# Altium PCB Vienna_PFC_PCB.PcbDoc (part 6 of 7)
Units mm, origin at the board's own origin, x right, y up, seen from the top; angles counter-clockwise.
Board outline 447.04 x 302.51 mm, 6 copper layers (Top Layer, Signal Layer 1, Signal Layer 2, Signal Layer 3, Signal Layer 4, Bottom Layer), stack 1.231 mm thick; 630 components, 255 nets, 1656 pads, 941 vias.
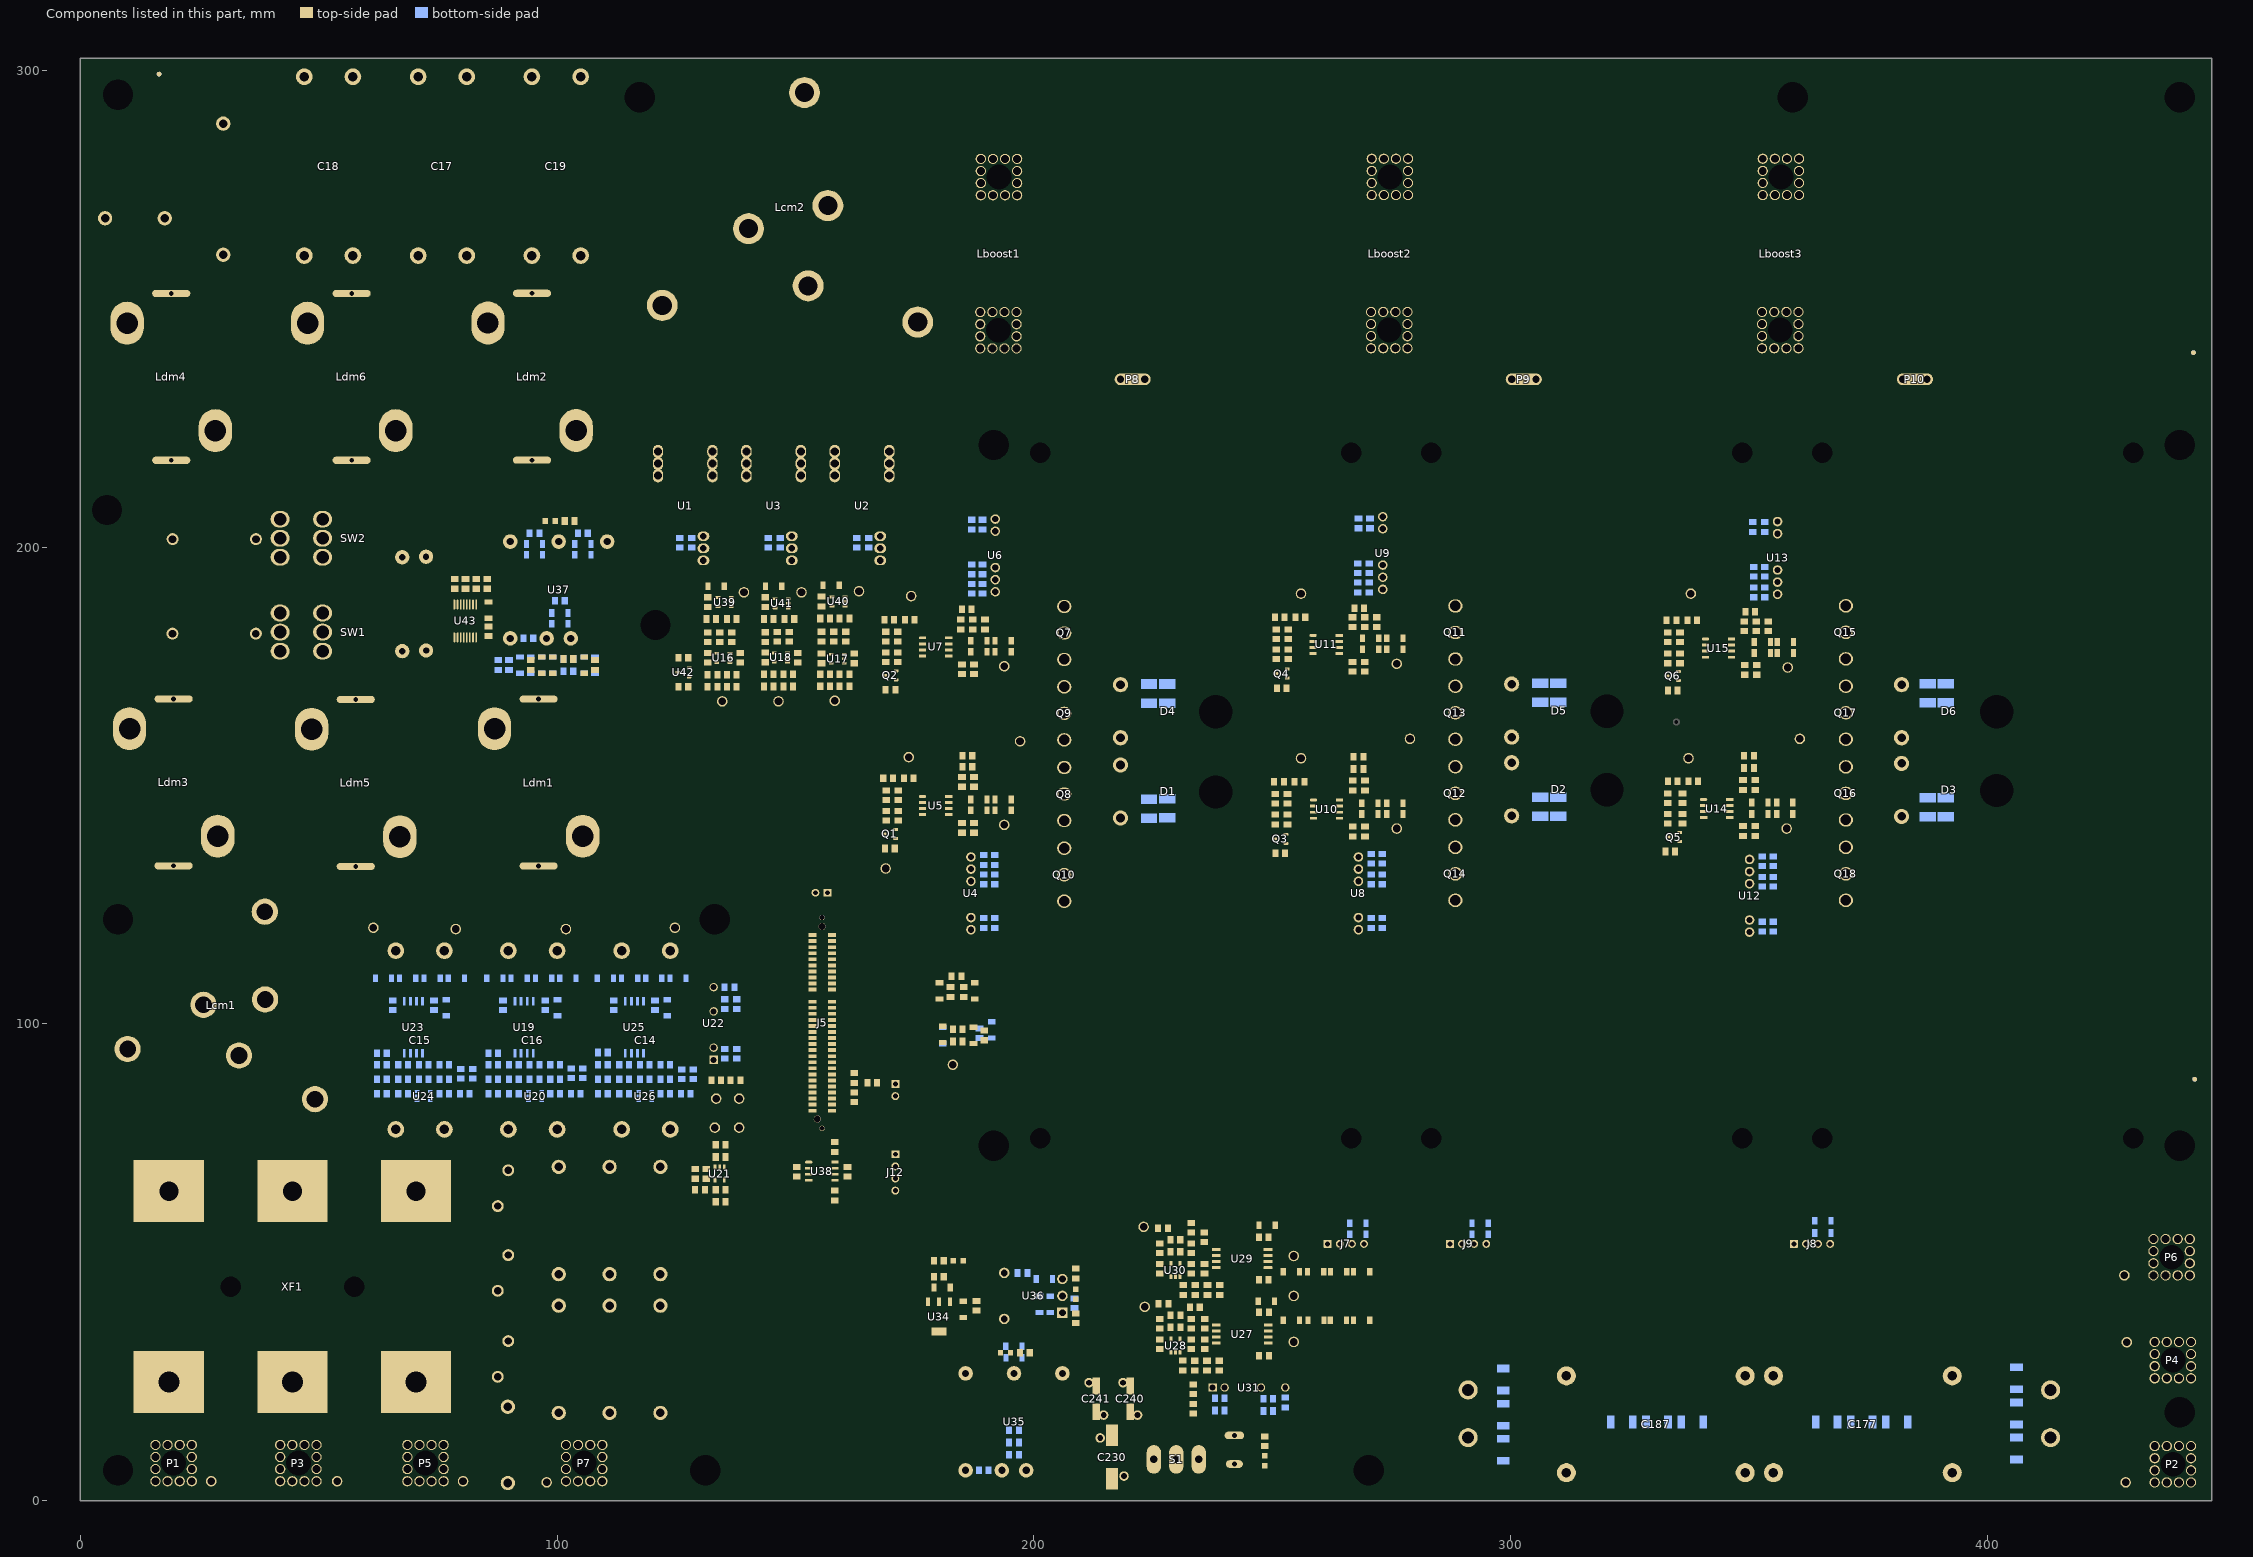
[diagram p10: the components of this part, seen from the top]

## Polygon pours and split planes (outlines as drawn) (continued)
NetLdm2_1 on Signal Layer 4 "NONET_L-01_P-001" (solid, remove dead copper, pour order 1302): 27 vertices, not listed, extent 46.99,175.26 107.442,231.648
NetLdm6_1 on Signal Layer 4 "NONET_L-01_P-001" (solid, remove dead copper, pour order 1292): 47.752,196.596 48.26,196.088 53.848,196.088 54.356,196.596 54.61,196.85 54.61,207.518 63.5,216.408 70.866,223.774 70.866,228.346 68.58,230.632 53.594,230.632 43.434,230.632 40.894,228.092 40.894,212.852 47.752,205.994
NetC16_2 on Signal Layer 4 "NONET_L-01_P-001" (solid, remove dead copper, pour order 1282): 27 vertices, not listed, extent 34.544,156.21 99.06,189.23
NetC14_2 on Signal Layer 4 "NONET_L-01_P-001" (solid, remove dead copper, pour order 1260): 30 vertices, not listed, extent 10.414,154.686 52.07,209.296
NetC15_2 on Signal Layer 4 "NONET_L-01_P-001" (solid, remove dead copper, pour order 1272): 31 vertices, not listed, extent 2.54,154.432 38.862,230.124
NetC8_2 on Signal Layer 4 "NONET_L-01_P-001" (solid, remove dead copper, pour order 1226): 32 vertices, not listed, extent 26.292,81.156 70.104,146.434
NetC9_2 on Signal Layer 4 "NONET_L-01_P-001" (solid, remove dead copper, pour order 1216): 17 vertices, not listed, extent 2.54,90.17 32.258,146.812
NetD3_2 on Signal Layer 4 "NONET_L-01_P-001" (solid, pour order 1164): 362.287,237.744 366.859,233.172 362.287,233.172
NetD2_2 on Signal Layer 4 "NONET_L-01_P-001" (solid, pour order 1150): 280.162,237.578 284.734,233.006 280.162,233.006
NetD1_2 on Signal Layer 4 "NONET_L-01_P-001" (solid, pour order 1138): 197.949,237.744 202.521,233.172 197.949,233.172
NetD3_2 on Signal Layer 4 "NONET_L-01_P-001" (solid, pour order 1126): 366.903,207.137 361.061,212.979 366.903,212.979
NetD2_2 on Signal Layer 4 "NONET_L-01_P-001" (solid, pour order 1116): 331.089,212.725 325.247,206.883 325.247,212.725
NetD2_2 on Signal Layer 4 "NONET_L-01_P-001" (solid, pour order 1106): 286.004,207.645 280.162,213.487 286.004,213.487
NetD1_2 on Signal Layer 4 "NONET_L-01_P-001" (solid, pour order 1096): 249.682,214.63 243.84,208.788 243.84,214.63
NetD1_2 on Signal Layer 4 "NONET_L-01_P-001" (solid, pour order 1088): 203.498,207.518 197.656,213.36 203.498,213.36
V_N_MEAS on Signal Layer 4 "NONET_L-01_P-001" (solid, remove dead copper, pour order 843): 135.636,101.6 61.468,101.6 61.214,101.854 61.214,110.49 135.636,110.49
GND5 on Signal Layer 4 "NONET_L-01_P-001" (solid, remove dead copper, pour order 520): 346.71,197.866 346.71,137.668 346.71,126.746 361.95,126.746 361.95,197.866
GND3 on Signal Layer 4 "NONET_L-01_P-001" (solid, remove dead copper, pour order 510): 264.922,198.628 264.922,138.43 264.922,127.508 280.162,127.508 280.162,198.628
GND1 on Signal Layer 4 "NONET_L-01_P-001" (solid, remove dead copper, pour order 502): 182.88,198.12 182.88,137.922 182.88,127.762 198.12,127.762 198.12,198.12
NetLcm1_3 on Signal Layer 4 "NONET_L-01_P-001" (solid, remove dead copper, pour order 64): 24 vertices, not listed, extent 34.29,56.896 91.694,109.22
NetLcm1_1 on Signal Layer 4 "NONET_L-01_P-001" (solid, remove dead copper, pour order 52): 25 vertices, not listed, extent 5.08,31.496 91.186,108.966
NetLcm1_5 on Signal Layer 4 "NONET_L-01_P-001" (solid, remove dead copper, pour order 40): 90.932,54.864 90.932,49.784 85.344,44.196 59.436,44.196 49.784,44.196 35.814,58.166 28.194,65.786 28.194,81.026 28.194,97.536 36.322,97.536 36.322,77.724 42.418,71.628 52.578,71.628 52.578,61.468 59.182,54.864
DGND on Signal Layer 4 "NONET_L-01_P-001" (solid, remove dead copper, pour order 550): 202.438,90.17 202.438,124.206 184.658,124.206 184.658,90.17
DGND on Signal Layer 4 "NONET_L-01_P-001" (solid, remove dead copper, pour order 560): 280.162,208.788 248.412,208.788 248.412,185.42 248.412,133.858 248.412,102.87 280.162,102.87 280.162,124.46 267.462,124.46 263.906,124.46 259.842,128.524 258.572,129.794 258.572,189.484 258.572,198.628 262.382,202.438 280.162,202.438
NetD1_2 on Signal Layer 4 "NONET_L-01_P-001" (solid, remove dead copper, pour order 622): 26 vertices, not listed, extent 186.69,153.162 262.89,251.206
NetD2_2 on Signal Layer 4 "NONET_L-01_P-001" (solid, remove dead copper, pour order 634): 26 vertices, not listed, extent 268.986,153.67 344.424,251.206
NetD3_2 on Signal Layer 4 "NONET_L-01_P-001" (solid, remove dead copper, pour order 646): 24 vertices, not listed, extent 351.028,153.67 422.91,251.206
V_BUS_M on Signal Layer 4 "NONET_L-01_P-001" (solid, remove dead copper, pour order 718): 17 vertices, not listed, extent 368.3,98.044 444.5,299.72
V_BUS_M on Signal Layer 4 "NONET_L-01_P-001" (solid, remove dead copper, pour order 763): 246.38,17.526 246.38,58.674 255.778,58.674 255.778,47.752 255.778,17.78
VBUSN on Signal Layer 4 "NONET_L-01_P-001" (solid, remove dead copper, pour order 918): 232.918,102.87 245.11,102.87 245.11,175.514 244.87,175.274 216.849,175.274 216.849,171.517 216.916,171.45 221.742,171.45 230.124,171.45 231.394,170.18 232.918,168.656
VBUSN on Signal Layer 4 "NONET_L-01_P-001" (solid, remove dead copper, pour order 948): 314.96,102.87 326.898,102.87 326.898,139.192 326.898,175.26 326.949,175.311 326.912,175.274 298.891,175.274 298.891,171.517 298.958,171.45 303.784,171.45 312.166,171.45 313.436,170.18 314.96,168.656
VBUSN on Signal Layer 4 "NONET_L-01_P-001" (solid, remove dead copper, pour order 980): 396.722,102.888 421.36,102.888 421.36,175.292 408.674,175.292 380.652,175.292 380.652,171.535 380.72,171.468 385.546,171.468 393.928,171.468 395.198,170.198 396.722,168.674
GND1 on Signal Layer 4 "NONET_L-01_P-001" (solid, remove dead copper, pour order 1012): 34 vertices, not listed, extent 198.628,124.206 208.534,189.23
GND3 on Signal Layer 4 "NONET_L-01_P-001" (solid, remove dead copper, pour order 1038): 25 vertices, not listed, extent 280.67,124.238 289.572,189.738
GND5 on Signal Layer 4 "NONET_L-01_P-001" (solid, remove dead copper, pour order 1058): 25 vertices, not listed, extent 362.458,124.238 371.36,188.976
GND_IN on Signal Layer 4 "NONET_L-01_P-001" (solid, remove dead copper, pour order 1464): 189.23,14.986 183.896,9.652 181.102,6.858 181.102,4.064 181.102,3.81 182.88,2.032 190.246,2.032 254,2.032 255.27,3.302 255.27,14.478 254.762,14.986
12V_IN on Signal Layer 4 "NONET_L-01_P-001" (solid, remove dead copper, pour order 1474): 261.62,62.23 260.35,60.96 260.35,52.578 261.62,51.308 295.91,51.308 296.164,51.308 297.18,52.324 297.18,58.928 297.18,60.706 295.656,62.23
VBUSP on Bottom Layer "NONET_L-01_P-001" (solid, remove dead copper, pour order 490): 302.768,66.802 302.768,46.99 274.32,46.99 274.32,2.032 424.18,2.032 424.18,54.61 424.18,66.802
+12V on Bottom Layer "NONET_L-01_P-001" (solid, remove dead copper, pour order 1184): 54 vertices, not listed, extent 88.392,2.54 240.538,200.914
+12V_D on Bottom Layer "NONET_L-01_P-001" (solid, remove dead copper, pour order 544): 198.12,208.534 181.356,208.534 165.354,192.532 165.354,132.08 181.864,115.57 202.438,115.57 202.438,124.206 185.42,124.206 181.864,124.206 177.8,128.27 176.53,129.54 176.53,189.23 176.53,198.374 180.34,202.184 198.12,202.184
VBUSN on Bottom Layer "NONET_L-01_P-001" (solid, remove dead copper, pour order 956): 314.96,102.87 326.898,102.87 326.898,139.192 326.898,175.26 326.949,175.311 326.912,175.274 298.891,175.274 298.891,171.517 298.958,171.45 303.784,171.45 312.166,171.45 313.436,170.18 314.96,168.656
VBUSN on Bottom Layer "NONET_L-01_P-001" (solid, remove dead copper, pour order 926): 232.918,102.87 245.11,102.87 245.11,175.514 244.87,175.274 216.849,175.274 216.849,171.517 216.916,171.45 221.742,171.45 230.124,171.45 231.394,170.18 232.918,168.656
VBUSN on Bottom Layer "NONET_L-01_P-001" (solid, remove dead copper, pour order 982): 396.722,102.888 421.36,102.888 421.36,175.292 408.674,175.292 380.652,175.292 380.652,171.535 380.72,171.468 385.546,171.468 393.928,171.468 395.198,170.198 396.722,168.674
VBUSP on Bottom Layer "NONET_L-01_P-001" (solid, remove dead copper, pour order 970): 393.7,88.9 381.254,88.9 381.254,142.748 382.778,144.272 393.7,144.272
VBUSP on Bottom Layer "NONET_L-01_P-001" (solid, remove dead copper, pour order 938): 312.166,87.884 299.72,87.884 299.72,142.748 301.244,144.272 312.166,144.272
VBUSP on Bottom Layer "NONET_L-01_P-001" (solid, remove dead copper, pour order 898): 230.124,66.294 217.678,66.294 217.678,142.748 219.202,144.272 230.124,144.272
+12V_D on Bottom Layer "NONET_L-01_P-001" (solid, remove dead copper, pour order 588): 361.95,207.772 330.2,207.772 330.2,184.404 330.2,132.842 330.2,102.87 361.95,102.87 361.95,123.444 349.25,123.444 345.694,123.444 341.63,127.508 340.36,128.778 340.36,188.468 340.36,197.612 344.17,201.422 361.95,201.422
GND on Bottom Layer "NONET_L-01_P-001" (solid, remove dead copper, pour order 841): 61.468,96.52 61.366,96.418 61.366,84.328 61.366,84.176 62.992,82.55 84.328,82.55 139.954,82.55 139.954,96.52
PE on Bottom Layer "NONET_L-01_P-001" (solid, remove dead copper, pour order 797): 123.698,2.286 123.698,64.77 98.298,64.77 98.298,2.286
+12V_D on Bottom Layer "NONET_L-01_P-001" (solid, remove dead copper, pour order 554): 202.438,90.17 202.438,124.206 184.15,124.206 184.15,90.17
NetC10_2 on Bottom Layer "NONET_L-01_P-001" (solid, remove dead copper, pour order 1246): 26 vertices, not listed, extent 36.068,120.904 110.236,145.796
DGND2 on Bottom Layer "NONET_L-01_P-001" (solid, remove dead copper, pour order 1482): 89.281,171.45 82.423,171.45 82.042,171.45 78.232,175.26 77.47,176.022 77.47,191.008 78.232,191.77 85.852,191.77 85.979,191.77 86.233,191.516 86.614,191.135 86.614,185.674 86.614,177.292 89.281,174.625
NetC20_1 on Bottom Layer "NONET_L-01_P-001" (solid, remove dead copper, pour order 1434): 12.7,276.86 10.16,274.32 10.16,264.16 12.7,261.62 13.97,260.35 30.48,260.35 33.02,262.89 33.782,263.652 33.782,273.812 30.734,276.86
NetC17_1 on Bottom Layer "NONET_L-01_P-001" (solid, remove dead copper, pour order 1422): 110.744,297.18 107.95,299.974 107.696,300.228 104.902,300.228 20.828,300.228 15.748,295.402 10.922,290.322 10.16,289.56 4.572,289.56 2.54,287.528 2.54,282.956 4.572,280.924 40.132,280.924 107.442,280.924 110.513,283.995
NetLboost3_1 on Bottom Layer "NONET_L-01_P-001" (solid, remove dead copper, pour order 1410): 38 vertices, not listed, extent 137.16,263.398 362.458,300.228
NetLboost2_1 on Bottom Layer "NONET_L-01_P-001" (solid, remove dead copper, pour order 1398): 20 vertices, not listed, extent 148.844,265.176 280.416,293.37
NetLboost1_1 on Bottom Layer "NONET_L-01_P-001" (solid, remove dead copper, pour order 1386): 150.114,256.286 151.384,255.016 151.384,252.476 172.466,252.476 189.23,269.24 195.58,269.24 198.374,272.034 198.374,282.448 197.612,283.21 178.054,283.21 152.4,257.556
NetLcm2_3 on Bottom Layer "NONET_L-01_P-001" (solid, remove dead copper, pour order 1374): 161.29,247.65 161.29,231.14 163.83,228.6 163.83,214.122 167.64,210.312 173.99,210.312 177.492,210.312 180.34,212.658 180.34,236.982 180.34,248.92 177.8,251.46 164.754,251.46
NetLcm2_5 on Bottom Layer "NONET_L-01_P-001" (solid, remove dead copper, pour order 1362): 32 vertices, not listed, extent 118.618,213.36 159.004,299.72
NetLcm2_1 on Bottom Layer "NONET_L-01_P-001" (solid, remove dead copper, pour order 1350): 123.444,254.254 117.856,248.666 120.65,245.872 128.27,238.252 128.27,228.092 128.27,215.392 129.794,213.868 130.302,213.36 133.35,213.36 134.112,213.36 135.128,214.376 135.636,214.884 135.636,235.966 135.636,242.062 131.318,246.38
NetC19_2 on Bottom Layer "NONET_L-01_P-001" (solid, remove dead copper, pour order 1340): 25 vertices, not listed, extent 77.47,212.852 125.222,264.16
NetC17_2 on Bottom Layer "NONET_L-01_P-001" (solid, remove dead copper, pour order 1330): 34 vertices, not listed, extent 44.196,213.614 143.51,278.13
NetC18_2 on Bottom Layer "NONET_L-01_P-001" (solid, remove dead copper, pour order 1314): 51 vertices, not listed, extent 5.08,205.232 162.814,278.13
NetLdm6_1 on Bottom Layer "NONET_L-01_P-001" (solid, remove dead copper, pour order 1310): 47.752,196.596 48.26,196.088 53.848,196.088 54.356,196.596 54.61,196.85 54.61,207.518 63.5,216.408 70.866,223.774 70.866,228.346 68.58,230.632 53.594,230.632 43.434,230.632 40.894,228.092 40.894,212.852 47.752,205.994
NetLdm2_1 on Bottom Layer "NONET_L-01_P-001" (solid, remove dead copper, pour order 1300): 27 vertices, not listed, extent 46.99,175.26 107.442,231.648
NetC16_2 on Bottom Layer "NONET_L-01_P-001" (solid, remove dead copper, pour order 1280): 27 vertices, not listed, extent 34.544,156.21 99.06,189.23
NetC15_2 on Bottom Layer "NONET_L-01_P-001" (solid, remove dead copper, pour order 1270): 31 vertices, not listed, extent 2.54,154.432 38.862,230.124
NetC14_2 on Bottom Layer "NONET_L-01_P-001" (solid, remove dead copper, pour order 1258): 30 vertices, not listed, extent 10.414,154.686 52.07,209.296
NetC9_2 on Bottom Layer "NONET_L-01_P-001" (solid, remove dead copper, pour order 1214): 17 vertices, not listed, extent 2.54,90.17 32.258,146.812
NetC8_2 on Bottom Layer "NONET_L-01_P-001" (solid, remove dead copper, pour order 1224): 32 vertices, not listed, extent 26.292,81.156 70.104,146.434
NetD3_2 on Bottom Layer "NONET_L-01_P-001" (solid, pour order 1172): 362.287,237.744 366.859,233.172 362.287,233.172
NetD2_2 on Bottom Layer "NONET_L-01_P-001" (solid, pour order 1148): 280.162,237.744 284.734,233.172 280.162,233.172
NetD1_2 on Bottom Layer "NONET_L-01_P-001" (solid, pour order 1136): 198.203,237.744 202.775,233.172 198.203,233.172
NetD3_2 on Bottom Layer "NONET_L-01_P-001" (solid, pour order 1084): 367.157,206.883 361.315,212.725 367.157,212.725
NetD2_2 on Bottom Layer "NONET_L-01_P-001" (solid, pour order 1082): 331.343,212.979 325.501,207.137 325.501,212.979
NetD2_2 on Bottom Layer "NONET_L-01_P-001" (solid, pour order 1080): 286.004,207.645 280.162,213.487 286.004,213.487
NetD1_2 on Bottom Layer "NONET_L-01_P-001" (solid, pour order 1078): 203.327,207.645 197.485,213.487 203.327,213.487
NetTVS1_1 on Bottom Layer "NONET_L-01_P-001" (solid, remove dead copper, pour order 1072): 24 vertices, not listed, extent 86.487,18.034 96.139,63.246
GND5 on Bottom Layer "NONET_L-01_P-001" (solid, remove dead copper, pour order 518): 346.71,197.866 346.71,137.668 346.71,126.746 361.95,126.746 361.95,197.866
GND3 on Bottom Layer "NONET_L-01_P-001" (solid, remove dead copper, pour order 508): 264.922,198.628 264.922,138.43 264.922,127.508 280.162,127.508 280.162,198.628
GND1 on Bottom Layer "NONET_L-01_P-001" (solid, remove dead copper, pour order 500): 182.88,198.12 182.88,137.922 182.88,127.762 198.12,127.762 198.12,198.12
VBUSP on Bottom Layer "NONET_L-01_P-001" (solid, pour order 484): 421.64,99.06 420.37,99.06 217.678,99.06 217.678,66.294 421.64,66.294
NetLcm1_3 on Bottom Layer "NONET_L-01_P-001" (solid, remove dead copper, pour order 56): 24 vertices, not listed, extent 34.29,56.769 91.694,109.093
NetLcm1_1 on Bottom Layer "NONET_L-01_P-001" (solid, remove dead copper, pour order 44): 25 vertices, not listed, extent 5.08,31.496 90.932,108.966
NetLcm1_5 on Bottom Layer "NONET_L-01_P-001" (solid, remove dead copper, pour order 32): 90.932,54.61 90.932,49.784 85.09,43.942 59.182,43.942 50.292,43.942 27.94,66.294 27.94,80.772 27.94,97.282 36.068,97.282 36.068,77.47 42.164,71.374 52.324,71.374 52.324,61.214 58.928,54.61
+12V_D on Bottom Layer "NONET_L-01_P-001" (solid, remove dead copper, pour order 558): 280.162,208.788 248.412,208.788 248.412,185.42 248.412,133.858 248.412,102.87 280.162,102.87 280.162,124.46 267.462,124.46 263.906,124.46 259.842,128.524 258.572,129.794 258.572,189.484 258.572,198.628 262.382,202.438 280.162,202.438
NetD1_2 on Bottom Layer "NONET_L-01_P-001" (solid, remove dead copper, pour order 620): 26 vertices, not listed, extent 186.69,153.162 262.89,251.206
NetD2_2 on Bottom Layer "NONET_L-01_P-001" (solid, remove dead copper, pour order 632): 26 vertices, not listed, extent 268.986,153.67 344.424,251.206
NetD3_2 on Bottom Layer "NONET_L-01_P-001" (solid, remove dead copper, pour order 644): 24 vertices, not listed, extent 351.028,153.67 422.91,251.206
V_BUS_M on Bottom Layer "NONET_L-01_P-001" (solid, remove dead copper, pour order 726): 18 vertices, not listed, extent 368.3,98.044 444.5,299.72
VBUSN on Bottom Layer "NONET_L-01_P-001" (solid, remove dead copper, pour order 874): 230.124,170.18 219.456,170.18 218.186,170.18 216.662,171.704 216.662,174.498 230.124,174.498
VBUSP on Bottom Layer "NONET_L-01_P-001" (solid, remove dead copper, pour order 876): 230.124,144.018 230.124,140.97 216.916,140.97 216.916,143.256 216.916,143.51 217.678,144.272 230.124,144.272
GND1 on Bottom Layer "NONET_L-01_P-001" (solid, remove dead copper, pour order 998): 34 vertices, not listed, extent 198.628,124.206 208.534,189.23
V_BUS_M on Bottom Layer "NONET_L-01_P-001" (solid, remove dead copper, pour order 1002): 35 vertices, not listed, extent 204.978,102.87 229.616,168.402
GND3 on Bottom Layer "NONET_L-01_P-001" (solid, remove dead copper, pour order 1004): 25 vertices, not listed, extent 280.67,124.238 289.572,189.738
V_BUS_M on Bottom Layer "NONET_L-01_P-001" (solid, remove dead copper, pour order 1006): 34 vertices, not listed, extent 287.02,102.87 311.658,168.91
GND5 on Bottom Layer "NONET_L-01_P-001" (solid, remove dead copper, pour order 1008): 25 vertices, not listed, extent 362.458,124.238 371.36,188.976
V_BUS_M on Bottom Layer "NONET_L-01_P-001" (solid, remove dead copper, pour order 1010): 34 vertices, not listed, extent 368.554,102.87 393.192,168.91
NetD1_2 on Bottom Layer "NONET_L-01_P-001" (solid, pour order 1076): 248.92,213.868 243.078,208.026 243.078,213.868
GND_IN on Bottom Layer "NONET_L-01_P-001" (solid, remove dead copper, pour order 1462): 189.23,14.986 183.896,9.652 181.102,6.858 181.102,4.064 181.102,3.81 182.88,2.032 190.246,2.032 254,2.032 255.27,3.302 255.27,14.478 254.762,14.986

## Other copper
Top Layer:
  rectangle net +3.3V: 176.276,43.942 179.832,51.308
  region net V_BUS_M: 432.919,288.867 431.546,287.274 434.611,284.632 435.984,286.225
  rectangle net GND5: 353.314,181.61 355.854,183.134
  rectangle net GND3: 271.018,182.118 273.812,183.896
  rectangle net -5V6: 350.266,150.368 353.314,157.48
  rectangle net GND1: 188.976,181.864 191.77,183.388
  rectangle net -5V2: 186.436,150.876 189.484,157.48
  rectangle net GND1: 182.88,150.876 185.674,157.48
  region net +12V: 183.769,102.362 177.292,102.362 177.292,98.044 183.769,98.044
  region net GND: 183.769,97.536 177.292,97.536 177.292,93.218 183.769,93.218
  region net +12V_D: 190.373,102.362 184.15,102.362 184.15,98.044 190.373,98.044
  region net DGND: 190.627,97.282 184.277,97.282 184.277,93.218 190.627,93.218
  rectangle net DGND: 184.277,102.87 188.595,106.172
  rectangle net GND: 177.292,102.87 183.261,106.172
  rectangle net +3.3V_D: 184.277,106.934 191.77,110.744
  rectangle net +3.3V: 177.292,106.934 183.261,110.744
  rectangle net V_BUS_M: 423.164,23.876 444.754,42.418
  rectangle net NetP1_1: 2.54,13.208 29.21,31.75
  rectangle net NetP1_1: 14.224,2.286 29.464,31.75
  rectangle net NetP3_1: 33.528,2.032 56.388,31.75
  rectangle net NetP5_1: 59.436,2.286 81.534,31.75
  rectangle net GND: 130.81,169.926 132.334,173.99
  rectangle net GND: 154.686,177.292 156.21,180.086
  rectangle net GND: 142.875,177.37 144.399,180.164
  rectangle net NetC110_1: 133.096,166.37 136.144,171.45
  rectangle net NetC114_1: 144.907,166.37 147.955,171.45
  rectangle net GND: 130.81,177.038 132.588,180.848
  rectangle net GND: 155.78,178.181 156.718,179.197
  rectangle net +3.3V: 129.618,175.26 130.81,176.276
  rectangle net +3.3V: 141.683,175.26 142.875,176.276
  rectangle net +3.3V: 153.494,175.133 154.686,176.149
  rectangle net NetC160_1: 230.48,28.727 233.782,31.648
  rectangle net NetC169_1: 230.454,44.552 233.756,47.346
  region net NetC211_1: 209.55,38.608 209.55,40.132 205.486,40.132 205.486,38.608
  rectangle net +3.3V_D: 174.244,183.896 176.022,186.944
  rectangle net +3.3V_D: 168.148,174.244 169.672,176.53
  rectangle net +3.3V_D: 250.19,174.752 251.714,177.292
  rectangle net +3.3V_D: 256.286,184.404 257.81,187.452
  rectangle net +3.3V_D: 174.244,150.622 175.768,153.67
  rectangle net +3.3V_D: 168.275,140.97 169.799,143.256
  rectangle net +3.3V_D: 256.286,149.86 257.81,152.908
  rectangle net +3.3V_D: 249.936,139.954 251.968,142.494
  rectangle net +3.3V_D: 338.328,183.642 339.852,186.944
  rectangle net +3.3V_D: 332.232,173.99 333.756,176.276
  rectangle net +3.3V_D: 338.582,150.114 340.106,152.908
  rectangle net +3.3V_D: 332.232,140.208 334.264,142.621
  rectangle net DGND: 170.688,173.736 174.752,176.53
  rectangle net DGND: 170.688,181.864 172.974,185.674
  rectangle net DGND: 170.434,148.59 172.974,152.4
  rectangle net DGND: 170.434,140.462 174.752,143.256
  rectangle net DGND: 173.228,142.748 174.752,144.272
  rectangle net DGND: 173.228,176.022 174.752,177.546
  rectangle net DGND: 252.73,182.118 254.508,185.928
  rectangle net DGND: 252.73,173.99 256.54,177.038
  rectangle net DGND: 255.016,173.99 256.794,178.054
  rectangle net DGND: 252.476,147.574 254.508,151.638
  rectangle net DGND: 252.476,139.446 256.794,142.494
  rectangle net DGND: 255.016,141.986 256.794,143.51
  rectangle net DGND: 334.772,181.61 337.058,185.42
  rectangle net DGND: 334.772,173.482 339.09,176.276
  rectangle net DGND: 337.312,175.514 339.09,177.292
  rectangle net NetJ5_45: 330.708,181.356 332.74,183.896
  region net EN_PWM: 330.962,170.942 330.962,168.91 333.502,168.91 333.502,170.942
  rectangle net NetJ5_47: 332.232,147.828 333.756,150.368
  region net EN_PWM: 333.248,134.112 333.248,137.16 331.216,137.16 331.216,134.112
  region net NetJ5_42: 251.206,182.626 251.206,184.658 248.666,184.658 248.666,182.626
  region net EN_PWM: 251.46,133.35 251.46,136.906 249.428,136.906 249.428,133.35
  region net NetJ5_40: 251.46,148.082 251.46,150.114 248.92,150.114 248.92,148.082
  region net EN_PWM: 251.714,169.418 251.714,171.45 249.174,171.45 249.174,169.418
  region net NetJ5_37: 169.418,182.372 169.418,184.404 166.878,184.404 166.878,182.372
  region net EN_PWM: 169.672,168.91 169.672,170.942 167.132,170.942 167.132,168.91
  region net EN_PWM: 169.291,135.636 169.291,137.668 166.751,137.668 166.751,135.636
  region net NetJ5_41: 169.164,148.336 169.164,151.638 166.37,151.638 166.37,148.336
  rectangle net -5V1: 186.436,184.404 190.5,185.674
  rectangle net NetR12_2: 189.738,177.419 192.278,180.975
  rectangle net NetR12_2: 189.738,177.419 192.278,178.689
  rectangle net +20V1: 184.15,174.752 189.738,176.53
  rectangle net +20V1: 184.15,174.752 185.674,177.546
  rectangle net GND1: 184.15,171.45 188.214,173.99
  rectangle net NetR6_1: 183.896,182.372 187.706,183.642
  rectangle net NetR6_1: 183.896,180.848 185.674,183.007
  rectangle net NetR5_1: 184.15,149.098 188.214,150.368
  rectangle net NetR5_1: 184.15,147.574 185.674,150.368
  rectangle net NetR11_2: 189.738,144.272 192.278,147.701
  rectangle net NetR11_2: 189.738,144.145 192.278,145.415
  rectangle net +20V2: 184.15,141.478 188.214,143.256
  rectangle net +20V2: 184.15,142.494 185.674,144.272
  rectangle net GND1: 184.15,138.176 188.214,140.716
  rectangle net -5V3: 268.732,184.658 272.796,187.96
  rectangle net NetR23_1: 266.192,182.626 270.256,184.15
  rectangle net +20V3: 266.192,175.26 271.78,177.292
  rectangle net +20V3: 265.938,175.26 267.462,178.054
  rectangle net GND3: 265.938,171.45 270.002,174.498
  rectangle net -5V4: 268.478,150.368 271.018,157.48
  rectangle net NetR22_1: 266.7,148.336 269.748,149.606
  rectangle net NetR22_1: 266.192,146.812 267.716,149.606
  rectangle net NetR28_2: 271.78,143.51 274.32,147.066
  rectangle net +20V4: 266.192,140.716 270.256,142.494
  rectangle net +20V4: 266.192,141.732 267.716,143.51
  rectangle net GND3: 265.684,137.414 270.256,139.954
  rectangle net -5V5: 350.774,183.642 354.838,187.198
  rectangle net NetR39_1: 348.234,182.118 352.044,183.134
  rectangle net NetR39_1: 348.234,180.594 349.758,182.88
  rectangle net NetR45_2: 354.076,177.038 356.362,180.848
  rectangle net +20V5: 348.488,174.498 353.822,176.53
  rectangle net +20V5: 348.488,175.768 349.758,177.292
  rectangle net GND5: 348.488,171.196 352.298,173.736
  rectangle net NetR38_1: 347.98,148.59 352.044,149.606
  rectangle net NetR38_1: 347.98,147.066 349.504,149.352
  rectangle net NetR44_2: 353.568,145.669 356.108,147.193
  rectangle net NetR44_2: 353.568,143.256 356.362,144.78
  rectangle net +20V6: 347.98,140.97 352.044,142.748
  rectangle net +20V6: 347.98,141.478 349.504,143.51
  rectangle net GND5: 347.98,137.16 352.044,139.954
  rectangle net NetR44_2: 353.568,143.256 356.362,147.193
  rectangle net GND1: 183.896,184.404 185.42,187.706
  rectangle net GND3: 265.938,184.912 267.716,188.214
  rectangle net GND3: 266.192,150.368 267.716,153.416
  rectangle net GND5: 348.234,183.896 349.758,187.198
  rectangle net GND5: 347.98,150.622 349.504,153.67
  rectangle net REF_3V3_2: 135.89,179.07 138.938,180.34
  rectangle net REF_3V3_2: 147.955,179.324 151.003,180.721
  rectangle net GND: 142.621,169.926 144.145,174.244
  rectangle net GND: 154.432,170.053 155.956,174.117
  rectangle net +5V: 130.302,62.738 131.826,66.04
  rectangle net GND: 132.588,61.976 134.112,66.04
  rectangle net GND: 128.016,68.834 132.08,70.358
  rectangle net NetC123_1: 130.556,66.802 133.35,68.072
  rectangle net GND: 132.08,71.374 133.858,75.438
  rectangle net REF_1V65: 134.874,71.374 135.89,75.438
  rectangle net +5V: 133.858,87.376 136.906,90.424
  rectangle net NetC227_1: 131.572,87.376 133.096,93.472
  rectangle net GND: 137.668,87.122 139.192,90.678
  rectangle net +3.3V: 176.276,39.37 178.308,51.308
  rectangle net GND: 180.594,43.688 183.896,48.8
  rectangle net +5V: 184.404,41.148 189.738,44.528
  rectangle net GND: 184.658,37.084 191.008,40.386
  rectangle net NetC211_1: 204.978,38.608 211.328,40.894
  rectangle net +5V: 203.2,48.006 209.804,49.53
  rectangle net GND_IN: 211.074,2.286 221.742,7.62
  rectangle net NetC206_1: 211.328,11.176 221.488,16.002
  rectangle net GND_IN: 189.992,2.032 195.58,15.748
  rectangle net NetC206_1: 196.088,4.826 200.914,15.748
  rectangle net GND: 182.626,19.05 192.532,33.274
  rectangle net +12V: 198.882,19.05 209.042,33.274
  rectangle net +12V: 207.772,19.05 210.058,37.846
  rectangle net +5V: 203.2,44.958 207.264,49.53
  rectangle net +5V: 232.41,19.558 235.966,23.114
  rectangle net GND: 233.934,17.526 237.236,19.05
  rectangle net GND: 230.124,25.654 239.776,27.94
  rectangle net GND: 225.552,27.94 229.87,30.226
  rectangle net GND: 225.552,29.464 227.33,32.512
  rectangle net +3.3V: 225.552,33.528 229.108,34.544
  rectangle net +3.3V: 235.458,28.702 239.776,30.226
  rectangle net GND: 227.584,40.64 229.87,44.958
  rectangle net GND: 229.362,40.64 231.14,43.752
  rectangle net GND: 227.584,44.958 229.87,45.974
  rectangle net GND: 230.632,42.164 239.776,43.688
  rectangle net GND: 237.236,36.576 239.776,42.672
  rectangle net +3.3V: 235.712,44.45 239.776,45.974
  rectangle net +3.3V: 224.028,49.276 229.108,50.495
  rectangle net GND: 227.33,56.388 229.108,59.69
  rectangle net GND: 237.49,52.578 239.014,54.864
  rectangle net 5V_M: 248.666,29.464 250.444,33.274
  rectangle net V_BUS_M: 246.634,19.558 247.904,31.242
  rectangle net 5V_M: 249.428,18.288 251.206,33.274
  rectangle net V_BUS_M: 246.38,18.288 248.92,24.892
  rectangle net V_BUS_M: 246.634,28.956 247.65,58.674
  rectangle net V_BUS_M: 246.634,52.324 249.936,53.848
  rectangle net 5V_M: 248.666,45.466 250.698,49.022
  rectangle net V_BUS_M: 246.888,36.576 249.936,37.846
  rectangle net NetC161_1: 248.666,38.862 250.952,42.672
  rectangle net NetC170_1: 248.666,54.61 251.206,58.674
  rectangle net NetR111_1: 255.27,37.084 257.81,38.608
  rectangle net NetR109_1: 260.35,37.084 262.89,38.608
  rectangle net NetR108_1: 265.176,37.084 267.462,38.608
  rectangle net NetR123_1: 255.27,47.244 257.81,48.768
  rectangle net NetR121_1: 260.35,47.244 262.636,48.768
  rectangle net NetR120_1: 265.176,47.244 267.462,48.768
  rectangle net V_BUS_M: 251.714,37.084 252.73,47.244
  rectangle net V_BUS_M: 247.396,43.688 252.476,44.45
  rectangle net V_BUS_M: 252.222,41.91 255.778,43.942
  rectangle net VBUSP: 269.748,35.306 271.272,38.608
  rectangle net VBUSN: 269.748,45.466 271.272,49.022
  rectangle net NetR23_1: 265.938,181.356 267.716,184.15
  rectangle net GND1: 182.88,184.15 185.674,190.246
  region net GND1: 188.468,168.656 188.468,171.704 184.15,171.704 184.15,168.656
  region net GND1: 182.88,140.716 182.88,136.906 187.452,136.906 187.452,140.716
  rectangle net GND3: 264.922,184.658 267.716,190.754
  region net GND3: 270.256,170.18 270.256,173.228 265.938,173.228 265.938,170.18
  region net GND3: 267.716,157.48 264.922,157.48 264.922,150.368 267.716,150.368
  rectangle net GND5: 346.71,183.896 349.758,188.722
  region net GND5: 349.758,157.48 346.71,157.48 346.71,150.368 349.758,150.368
  rectangle net DGND: 183.261,90.17 185.039,92.456
  rectangle net +12V: 209.804,18.796 220.98,20.32
  rectangle net GND: 130.175,189.484 132.334,192.532
  rectangle net -15V: 136.906,184.15 138.43,186.69
  rectangle net GND: 135.128,183.134 136.144,185.674
  rectangle net GND: 137.668,175.26 140.462,176.276
  rectangle net GND: 142.494,188.722 144.399,192.532
  rectangle net -15V: 148.971,183.896 150.495,186.436
  rectangle net GND: 147.193,183.261 148.209,185.674
  rectangle net GND: 151.003,175.26 152.4,176.276
  rectangle net GND: 154.305,188.976 156.337,192.786
  rectangle net -15V: 160.528,184.023 162.052,186.563
  rectangle net GND: 158.496,183.261 159.893,185.801
  rectangle net REF_3V3_2: 159.766,179.451 162.814,180.848
  rectangle net NetC112_1: 156.718,166.497 159.766,171.577
  rectangle net GND: 123.952,169.799 126.111,177.546
  rectangle net GND: 211.582,20.828 230.124,28.194
  region net +5V: 150.114,68.58 148.59,68.58 148.59,67.564 150.114,67.564
  region net GND: 150.114,70.358 148.59,70.358 148.59,69.342 150.114,69.342
  region net +3.3V: 158.75,67.564 157.734,67.564 157.734,64.516 158.75,64.516
  region net NetR178_1: 159.004,72.39 157.48,72.39 157.48,70.612 159.004,70.612
  rectangle net GND: 161.544,175.006 164.592,176.209
  region net GND: 159.004,76.2 157.48,76.2 157.48,74.422 159.004,74.422
  rectangle net +3.3V: 102.616,175.514 110.744,177.8
  rectangle net +3.3V_2: 93.472,175.514 102.108,177.546
  rectangle net DGND2: 86.614,171.45 102.108,175.006
  rectangle net DGND2: 84.836,182.88 86.36,185.42
  rectangle net NetR29_2: 271.78,177.8 274.574,181.61
  pour cut-out: 370.867,55.118 ccw(c368.327,55.118) 368.327,57.658 358.14,57.658 ccw(c358.14,55.118) 355.6,55.118 355.6,52.578 ccw(c358.14,52.578) 358.14,50.038 368.327,50.038 ccw(c368.327,52.578) 370.867,52.578
  pour cut-out: 186.639,251.028 188.163,251.028 ccw(c188.163,249.504) 186.639,249.504
  pour cut-out: 123.698,64.77 122.682,64.77 cw(c122.682,63.754) 123.698,63.754
  pour cut-out: 98.298,64.77 98.298,63.754 cw(c99.314,63.754) 99.314,64.77
  pour cut-out: 186.665,212.065 187.681,212.065 cw(c187.681,213.081) 186.665,213.081
  pour cut-out: 2.54,34.798 3.556,34.798 cw(c3.556,35.814) 2.54,35.814
  pour cut-out: 27.94,97.561 27.94,96.545 cw(c28.956,96.545) 28.956,97.561
  pour cut-out: 36.424,97.511 35.408,97.511 cw(c35.408,96.495) 36.424,96.495
  pour cut-out: 91.68,73.538 90.664,73.538 cw(c90.664,72.522) 91.68,72.522
  pour cut-out: 368.3,299.72 369.824,299.72 ccw(c369.824,298.196) 368.3,298.196
  pour cut-out: 368.224,286.969 368.224,288.493 ccw(c369.748,288.493) 369.748,286.969
  pour cut-out: 434.264,270.459 434.264,271.983 ccw(c435.788,271.983) 435.788,270.459
  pour cut-out: 434.238,253.314 435.762,253.314 ccw(c435.762,251.79) 434.238,251.79
  pour cut-out: 425.958,235.737 427.482,235.737 ccw(c427.482,234.213) 425.958,234.213
  pour cut-out: 422.935,233.451 422.935,231.927 ccw(c421.411,231.927) 421.411,233.451
  pour cut-out: 268.935,251.079 270.459,251.079 ccw(c270.459,249.555) 268.935,249.555
  pour cut-out: 350.977,251.181 352.501,251.181 ccw(c352.501,249.657) 350.977,249.657
  pour cut-out: 198.501,251.282 198.501,249.758 ccw(c196.977,249.758) 196.977,251.282
  pour cut-out: 280.467,251.257 280.467,249.733 ccw(c278.943,249.733) 278.943,251.257
  pour cut-out: 362.509,251.257 362.509,249.733 ccw(c360.985,249.733) 360.985,251.257
  pour cut-out: 262.941,213.284 261.417,213.284 ccw(c261.417,214.808) 262.941,214.808
  pour cut-out: 268.935,213.309 268.935,214.833 ccw(c270.459,214.833) 270.459,213.309
  pour cut-out: 350.977,212.039 350.977,213.563 ccw(c352.501,213.563) 352.501,212.039
  pour cut-out: 344.5,212.039 342.976,212.039 ccw(c342.976,213.563) 344.5,213.563
  pour cut-out: 198.196,208.585 198.196,207.061 ccw(c196.672,207.061) 196.672,208.585
  pour cut-out: 280.187,208.813 280.187,207.289 ccw(c278.663,207.289) 278.663,208.813
  pour cut-out: 361.975,207.797 361.975,206.273 ccw(c360.451,206.273) 360.451,207.797
  pour cut-out: 248.361,208.839 249.885,208.839 ccw(c249.885,207.315) 248.361,207.315
  pour cut-out: 330.149,207.823 331.673,207.823 ccw(c331.673,206.299) 330.149,206.299
  pour cut-out: 198.145,202.184 196.621,202.184 ccw(c196.621,203.708) 198.145,203.708
  pour cut-out: 280.187,202.413 278.663,202.413 ccw(c278.663,203.937) 280.187,203.937
  pour cut-out: 362.001,201.397 360.477,201.397 ccw(c360.477,202.921) 362.001,202.921
  pour cut-out: 264.897,198.653 266.421,198.653 ccw(c266.421,197.129) 264.897,197.129
  pour cut-out: 346.659,197.866 348.183,197.866 ccw(c348.183,196.342) 346.659,196.342
  pour cut-out: 182.804,198.196 184.328,198.196 ccw(c184.328,196.672) 182.804,196.672
  pour cut-out: 198.171,198.171 198.171,196.647 ccw(c196.647,196.647) 196.647,198.171
  pour cut-out: 362.026,197.917 362.026,196.393 ccw(c360.502,196.393) 360.502,197.917
  pour cut-out: 182.855,127.711 182.855,129.235 ccw(c184.379,129.235) 184.379,127.711
  pour cut-out: 264.922,127.508 264.922,129.032 ccw(c266.446,129.032) 266.446,127.508
  pour cut-out: 346.659,126.695 346.659,128.219 ccw(c348.183,128.219) 348.183,126.695
  pour cut-out: 201.905,191.745 201.905,193.269 ccw(c203.429,193.269) 203.429,191.745
  pour cut-out: 285.674,191.694 285.674,193.218 ccw(c287.198,193.218) 287.198,191.694
  pour cut-out: 365.735,194.285 365.735,195.809 ccw(c367.259,195.809) 367.259,194.285
  pour cut-out: 243.891,177.749 242.367,177.749 ccw(c242.367,179.273) 243.891,179.273
  pour cut-out: 326.39,178.791 324.866,178.791 ccw(c324.866,180.315) 326.39,180.315
  pour cut-out: 422.91,178.562 421.386,178.562 ccw(c421.386,180.086) 422.91,180.086
  pour cut-out: 245.308,175.458 245.308,173.934 ccw(c243.784,173.934) 243.784,175.458
  pour cut-out: 298.933,175.311 300.457,175.311 ccw(c300.457,173.787) 298.933,173.787
  pour cut-out: 327.685,175.285 327.685,173.761 ccw(c326.161,173.761) 326.161,175.285
  pour cut-out: 379.959,175.285 381.483,175.285 ccw(c381.483,173.761) 379.959,173.761
  pour cut-out: 421.492,175.408 421.492,173.884 ccw(c419.968,173.884) 419.968,175.408
  pour cut-out: 444.525,83.769 443.001,83.769 ccw(c443.001,85.293) 444.525,85.293
  pour cut-out: 274.295,47.015 275.819,47.015 ccw(c275.819,45.491) 274.295,45.491
  pour cut-out: 205.207,66.269 205.207,67.793 ccw(c206.731,67.793) 206.731,66.269
  pour cut-out: 198.12,124.206 cw(c198.12,119.888) 202.438,119.888 202.438,124.206
  pour cut-out: 275.844,124.46 cw(c275.844,120.142) 280.162,120.142 280.162,124.46
  pour cut-out: 357.632,123.444 cw(c357.632,119.126) 361.95,119.126 361.95,123.444
Signal Layer 1:
  region net V_BUS_M: 432.919,288.867 431.546,287.274 434.611,284.632 435.984,286.225
  rectangle net NetP5_1: 59.436,2.286 81.534,31.75
  rectangle net NetP3_1: 33.528,2.032 56.388,31.75
  rectangle net NetP1_1: 2.54,13.208 29.21,31.75
  rectangle net NetP1_1: 13.97,2.286 29.972,31.75
  rectangle net +12V_D: 184.277,100.076 192.151,102.362
  rectangle net +12V_D: 251.206,102.87 258.572,111.506
  rectangle net +12V_D: 331.724,102.87 339.09,112.086
  pour cut-out: 370.867,55.118 ccw(c368.327,55.118) 368.327,57.658 358.14,57.658 ccw(c358.14,55.118) 355.6,55.118 355.6,52.578 ccw(c358.14,52.578) 358.14,50.038 368.327,50.038 ccw(c368.327,52.578) 370.867,52.578
  pour cut-out: 186.639,251.028 188.163,251.028 ccw(c188.163,249.504) 186.639,249.504
  pour cut-out: 123.698,64.77 122.682,64.77 cw(c122.682,63.754) 123.698,63.754
  pour cut-out: 98.298,64.77 98.298,63.754 cw(c99.314,63.754) 99.314,64.77
  pour cut-out: 186.665,212.065 187.681,212.065 cw(c187.681,213.081) 186.665,213.081
  pour cut-out: 55.143,117.881 54.127,117.881 cw(c54.127,116.865) 55.143,116.865
  pour cut-out: 2.54,34.798 3.556,34.798 cw(c3.556,35.814) 2.54,35.814
  pour cut-out: 27.94,97.561 27.94,96.545 cw(c28.956,96.545) 28.956,97.561
  pour cut-out: 36.424,97.511 35.408,97.511 cw(c35.408,96.495) 36.424,96.495
  pour cut-out: 91.68,73.538 90.664,73.538 cw(c90.664,72.522) 91.68,72.522
  pour cut-out: 29.743,108.991 28.727,108.991 cw(c28.727,107.975) 29.743,107.975
  pour cut-out: 34.214,109.296 34.214,108.28 cw(c35.23,108.28) 35.23,109.296
  pour cut-out: 368.3,299.72 369.824,299.72 ccw(c369.824,298.196) 368.3,298.196
  pour cut-out: 368.224,286.969 368.224,288.493 ccw(c369.748,288.493) 369.748,286.969
  pour cut-out: 434.264,270.459 434.264,271.983 ccw(c435.788,271.983) 435.788,270.459
  pour cut-out: 434.238,253.314 435.762,253.314 ccw(c435.762,251.79) 434.238,251.79
  pour cut-out: 425.958,235.737 427.482,235.737 ccw(c427.482,234.213) 425.958,234.213
  pour cut-out: 422.935,233.451 422.935,231.927 ccw(c421.411,231.927) 421.411,233.451
  pour cut-out: 268.935,251.079 270.459,251.079 ccw(c270.459,249.555) 268.935,249.555
  pour cut-out: 350.977,251.181 352.501,251.181 ccw(c352.501,249.657) 350.977,249.657
  pour cut-out: 198.501,251.282 198.501,249.758 ccw(c196.977,249.758) 196.977,251.282
  pour cut-out: 280.467,251.257 280.467,249.733 ccw(c278.943,249.733) 278.943,251.257
  pour cut-out: 362.509,251.257 362.509,249.733 ccw(c360.985,249.733) 360.985,251.257
  pour cut-out: 262.941,213.284 261.417,213.284 ccw(c261.417,214.808) 262.941,214.808
  pour cut-out: 268.935,213.309 268.935,214.833 ccw(c270.459,214.833) 270.459,213.309
  pour cut-out: 350.977,212.039 350.977,213.563 ccw(c352.501,213.563) 352.501,212.039
  pour cut-out: 344.5,212.039 342.976,212.039 ccw(c342.976,213.563) 344.5,213.563
  pour cut-out: 198.196,208.585 198.196,207.061 ccw(c196.672,207.061) 196.672,208.585
  pour cut-out: 280.187,208.813 280.187,207.289 ccw(c278.663,207.289) 278.663,208.813
  pour cut-out: 361.975,207.797 361.975,206.273 ccw(c360.451,206.273) 360.451,207.797
  pour cut-out: 248.361,208.839 249.885,208.839 ccw(c249.885,207.315) 248.361,207.315
  pour cut-out: 330.149,207.823 331.673,207.823 ccw(c331.673,206.299) 330.149,206.299
  pour cut-out: 198.145,202.184 196.621,202.184 ccw(c196.621,203.708) 198.145,203.708
  pour cut-out: 280.187,202.413 278.663,202.413 ccw(c278.663,203.937) 280.187,203.937
  pour cut-out: 362.001,201.397 360.477,201.397 ccw(c360.477,202.921) 362.001,202.921
  pour cut-out: 264.897,198.653 266.421,198.653 ccw(c266.421,197.129) 264.897,197.129
  pour cut-out: 346.659,197.866 348.183,197.866 ccw(c348.183,196.342) 346.659,196.342
  pour cut-out: 182.804,198.196 184.328,198.196 ccw(c184.328,196.672) 182.804,196.672
  pour cut-out: 198.171,198.171 198.171,196.647 ccw(c196.647,196.647) 196.647,198.171
  pour cut-out: 280.213,198.679 280.213,197.155 ccw(c278.689,197.155) 278.689,198.679
  pour cut-out: 362.026,197.917 362.026,196.393 ccw(c360.502,196.393) 360.502,197.917
  pour cut-out: 182.855,127.711 182.855,129.235 ccw(c184.379,129.235) 184.379,127.711
  pour cut-out: 264.922,127.508 264.922,129.032 ccw(c266.446,129.032) 266.446,127.508
  pour cut-out: 346.659,126.695 346.659,128.219 ccw(c348.183,128.219) 348.183,126.695
  pour cut-out: 201.905,191.745 201.905,193.269 ccw(c203.429,193.269) 203.429,191.745
  pour cut-out: 285.674,191.694 285.674,193.218 ccw(c287.198,193.218) 287.198,191.694
  pour cut-out: 365.735,194.285 365.735,195.809 ccw(c367.259,195.809) 367.259,194.285
  pour cut-out: 243.891,177.749 242.367,177.749 ccw(c242.367,179.273) 243.891,179.273
  pour cut-out: 326.39,178.791 324.866,178.791 ccw(c324.866,180.315) 326.39,180.315
  pour cut-out: 422.91,178.562 421.386,178.562 ccw(c421.386,180.086) 422.91,180.086
  pour cut-out: 215.875,175.311 217.399,175.311 ccw(c217.399,173.787) 215.875,173.787
  pour cut-out: 245.308,175.458 245.308,173.934 ccw(c243.784,173.934) 243.784,175.458
  pour cut-out: 298.933,175.311 300.457,175.311 ccw(c300.457,173.787) 298.933,173.787
  pour cut-out: 327.685,175.285 327.685,173.761 ccw(c326.161,173.761) 326.161,175.285
  pour cut-out: 379.959,175.285 381.483,175.285 ccw(c381.483,173.761) 379.959,173.761
  pour cut-out: 421.492,175.408 421.492,173.884 ccw(c419.968,173.884) 419.968,175.408
  pour cut-out: 444.525,83.769 443.001,83.769 ccw(c443.001,85.293) 444.525,85.293
  pour cut-out: 274.295,47.015 275.819,47.015 ccw(c275.819,45.491) 274.295,45.491
  pour cut-out: 205.207,66.269 205.207,67.793 ccw(c206.731,67.793) 206.731,66.269
  pour cut-out: 198.12,124.206 cw(c198.12,119.888) 202.438,119.888 202.438,124.206
  pour cut-out: 275.844,124.46 cw(c275.844,120.142) 280.162,120.142 280.162,124.46
  pour cut-out: 357.632,123.444 cw(c357.632,119.126) 361.95,119.126 361.95,123.444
